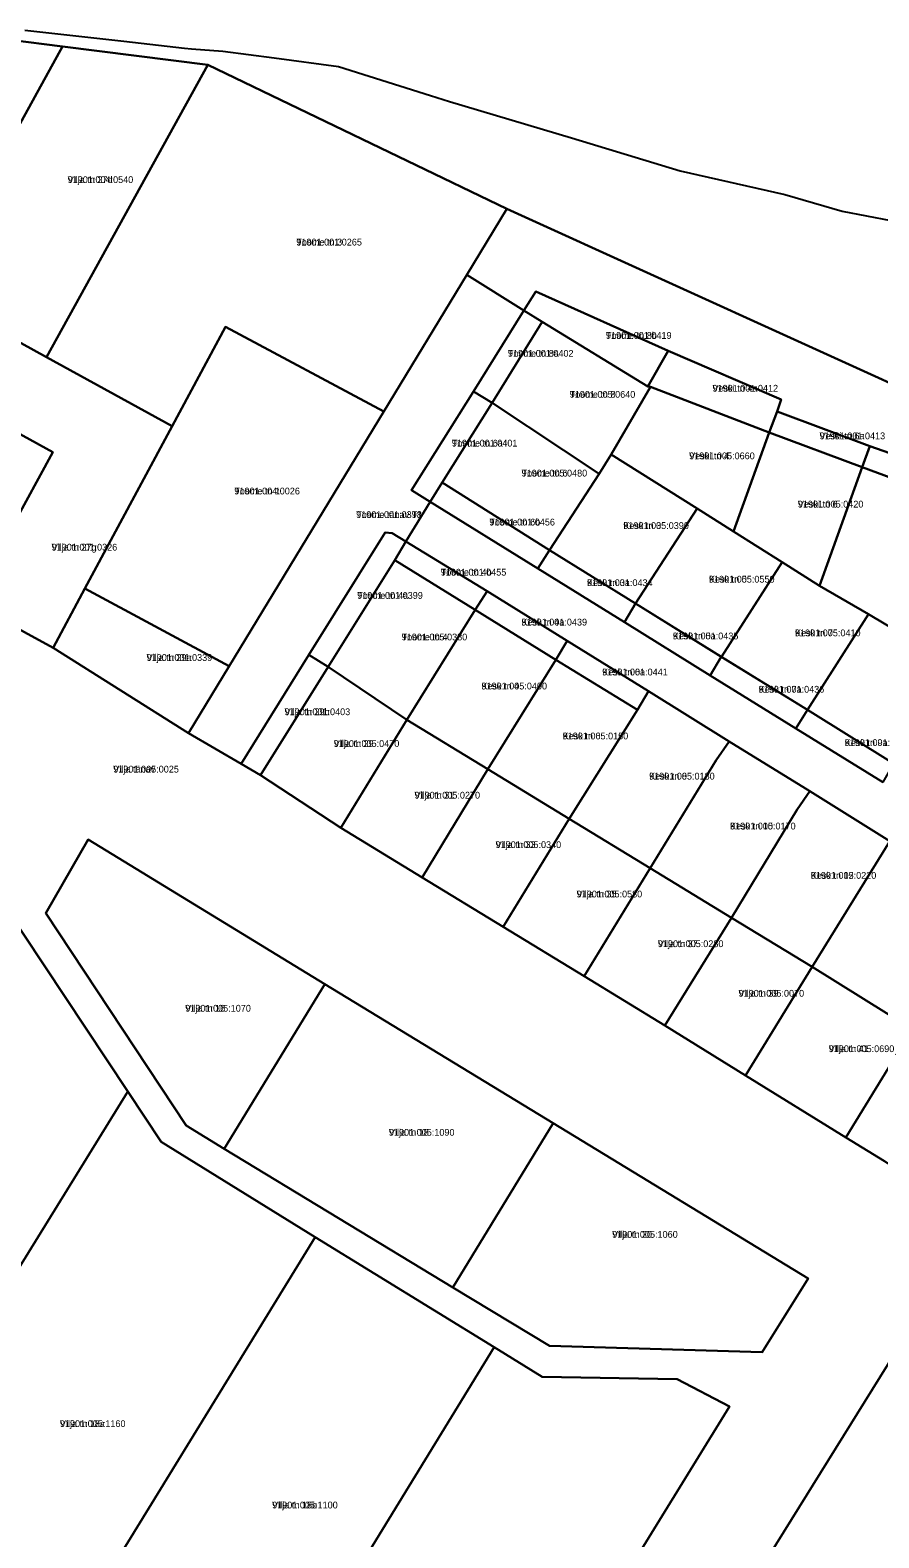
# Model space of a CAD drawing. Extents: x 675810 to 681273, y 6411190 to 6417565.
# Drawn here: x 678832.9 to 679020.6, y 6415637.7 to 6415971.1 of the extents above; entities that cross this region are included whole.
import ezdxf

# ---------------------------------------------------------------- set-up
doc = ezdxf.new("R2010")
doc.units = 0
for name, color, linetype in [('L_AADRESS', 7, 'Continuous'), ('PIIR', 7, 'Continuous'), ('TUNNUS', 7, 'Continuous')]:
    doc.layers.add(name, color=color, linetype=linetype)

msp = doc.modelspace()

# ---------------------------------------------------------------- linework, layer by layer
at = {"layer": 'PIIR'}
for points in [[(678816.91, 6415970.45), (678840.09, 6415967.49), (678810.26, 6415913.35), (678807.69, 6415914.78), (678793.59, 6415922.56), (678787.87, 6415925.69), (678793.94, 6415936.81)], [(678840.09, 6415967.49), (678872.23, 6415963.49), (678836.57, 6415898.82), (678819.7, 6415908.13), (678810.26, 6415913.35)], [(678872.23, 6415963.49), (678938.35, 6415931.63), (678929.48, 6415916.98), (678911.14, 6415886.77), (678876.17, 6415905.51), (678864.38, 6415883.51), (678836.57, 6415898.82)], [(678929.48, 6415916.98), (678938.35, 6415931.63), (679105.26, 6415855.66), (679114.18, 6415850.62), (679165.65, 6415822.55), (679204.44, 6415812.13), (679202.38, 6415803.59), (679183.64, 6415808.38), (679179.78, 6415809.54), (679156.58, 6415819.69), (679127.49, 6415833.35), (679099.54, 6415846.24), (679093.45, 6415836.45), (679084.93, 6415841.89), (679090.32, 6415850.54), (679057.56, 6415864.54), (679037.79, 6415872.39), (679018.58, 6415879.14), (678998.13, 6415886.78), (678998.97, 6415889.41), (678974.02, 6415900.22), (678944.77, 6415913.36), (678942.12, 6415909.13)], [(678879.6, 6415808.84), (678867.97, 6415815.62), (678876.92, 6415830.49), (678911.14, 6415886.77), (678929.48, 6415916.98), (678942.12, 6415909.13), (678931, 6415891.2), (678917.28, 6415869.38), (678921.37, 6415866.84), (678916, 6415858.06), (678913, 6415859.9), (678911.48, 6415860), (678894.53, 6415832.98)], [(678946.19, 6415906.63), (678942.12, 6415909.13), (678944.77, 6415913.36), (678974.02, 6415900.22), (678969.55, 6415892.35)], [(678935.09, 6415888.69), (678931, 6415891.2), (678942.12, 6415909.13), (678946.19, 6415906.63)], [(678811.02, 6415892.58), (678819.7, 6415908.13), (678836.57, 6415898.82), (678864.38, 6415883.51), (678845.04, 6415847.65), (678838.07, 6415834.5), (678819.79, 6415844.47), (678837.94, 6415877.79)], [(678911.14, 6415886.77), (678876.92, 6415830.49), (678845.04, 6415847.65), (678864.38, 6415883.51), (678876.17, 6415905.51)], [(678958.79, 6415873.03), (678935.09, 6415888.69), (678946.19, 6415906.63), (678969.55, 6415892.35), (678970.09, 6415892.21), (678961.44, 6415877.27)], [(678969.55, 6415892.35), (678974.02, 6415900.22), (678998.97, 6415889.41), (678998.13, 6415886.78), (678996.38, 6415882.15), (678970.09, 6415892.21)], [(678819.79, 6415844.47), (678792.22, 6415859.43), (678811.02, 6415892.58), (678837.94, 6415877.79)], [(678988.45, 6415860.25), (678980.42, 6415865.31), (678961.44, 6415877.27), (678970.09, 6415892.21), (678996.38, 6415882.15)], [(678921.37, 6415866.84), (678917.28, 6415869.38), (678931, 6415891.2), (678935.09, 6415888.69), (678924.03, 6415871.11)], [(678924.03, 6415871.11), (678935.09, 6415888.69), (678958.79, 6415873.03), (678947.77, 6415856.12)], [(678996.38, 6415882.15), (678998.13, 6415886.78), (679018.58, 6415879.14), (679016.9, 6415874.51)], [(679016.9, 6415874.51), (679007.49, 6415848.26), (678999.26, 6415853.44), (678988.45, 6415860.25), (678996.38, 6415882.15)], [(679016.9, 6415874.51), (679018.58, 6415879.14), (679037.79, 6415872.39), (679035.82, 6415867.44)], [(678958.79, 6415873.03), (678961.44, 6415877.27), (678980.42, 6415865.31), (678966.81, 6415844.36), (678947.77, 6415856.12)], [(679025.58, 6415837.61), (679018.34, 6415841.95), (679007.49, 6415848.26), (679016.9, 6415874.51), (679035.82, 6415867.44)], [(678921.37, 6415866.84), (678924.03, 6415871.11), (678947.77, 6415856.12), (678945.23, 6415852.06)], [(678980.42, 6415865.31), (678988.45, 6415860.25), (678999.26, 6415853.44), (678985.78, 6415832.52), (678966.81, 6415844.36)], [(678898.82, 6415830.31), (678894.53, 6415832.98), (678911.48, 6415860), (678913, 6415859.9), (678916, 6415858.06), (678913.57, 6415853.92)], [(678913.57, 6415853.92), (678916, 6415858.06), (678933.99, 6415847.04), (678931.37, 6415842.94)], [(678945.23, 6415852.06), (678947.77, 6415856.12), (678966.81, 6415844.36), (678964.34, 6415840.23)], [(678898.82, 6415830.31), (678913.57, 6415853.92), (678931.37, 6415842.94), (678916.25, 6415818.59)], [(678999.26, 6415853.44), (679007.49, 6415848.26), (679018.34, 6415841.95), (679004.82, 6415820.78), (678985.78, 6415832.52)], [(678838.07, 6415834.5), (678845.04, 6415847.65), (678876.92, 6415830.49), (678867.97, 6415815.62)], [(678931.37, 6415842.94), (678933.99, 6415847.04), (678951.71, 6415836.04), (678949.2, 6415831.89)], [(678916.25, 6415818.59), (678931.37, 6415842.94), (678949.2, 6415831.89), (678934.18, 6415807.66)], [(678964.34, 6415840.23), (678966.81, 6415844.36), (678985.77, 6415832.55), (678983.27, 6415828.44)], [(679025.58, 6415837.61), (679037.46, 6415830.49), (679034.34, 6415825.26), (679023.84, 6415808.91), (679004.82, 6415820.78), (679018.34, 6415841.95)], [(678949.2, 6415831.89), (678951.71, 6415836.04), (678969.69, 6415824.91), (678967.2, 6415820.8)], [(678883.9, 6415806.35), (678879.6, 6415808.84), (678894.53, 6415832.98), (678898.82, 6415830.31)], [(678983.27, 6415828.44), (678985.77, 6415832.55), (679004.82, 6415820.78), (679002.22, 6415816.67)], [(678883.9, 6415806.35), (678898.82, 6415830.31), (678916.25, 6415818.59), (678901.67, 6415794.69)], [(678934.18, 6415807.66), (678949.2, 6415831.89), (678967.2, 6415820.8), (678952.11, 6415796.73)], [(678952.11, 6415796.73), (678967.2, 6415820.8), (678969.69, 6415824.91), (678987.5, 6415813.81), (678984.61, 6415809.71), (678970.03, 6415785.8)], [(678901.67, 6415794.69), (678916.25, 6415818.59), (678934.18, 6415807.66), (678919.6, 6415783.76)], [(679002.22, 6415816.67), (679004.82, 6415820.78), (679023.84, 6415808.91), (679021.5, 6415804.84)], [(678970.03, 6415785.8), (678984.61, 6415809.71), (678987.5, 6415813.81), (679005.36, 6415802.84), (679002.54, 6415798.78), (678988.02, 6415774.82)], [(678919.6, 6415783.76), (678934.18, 6415807.66), (678952.11, 6415796.73), (678937.53, 6415772.83)], [(678988.02, 6415774.82), (679002.54, 6415798.78), (679005.36, 6415802.84), (679023.06, 6415791.8), (679005.89, 6415763.94)], [(678937.53, 6415772.83), (678952.11, 6415796.73), (678970.03, 6415785.8), (678955.46, 6415761.9)], [(678836.4, 6415775.85), (678845.75, 6415792.11), (678898.11, 6415760.17), (678875.88, 6415723.72), (678867.41, 6415728.89)], [(678836.4, 6415775.85), (678867.41, 6415728.89), (678875.88, 6415723.72), (678926.43, 6415693.08), (678947.76, 6415680.14), (678994.8, 6415678.72), (679004.98, 6415695.01), (678948.58, 6415729.39), (678898.11, 6415760.17), (678845.75, 6415792.11)], [(679023.06, 6415791.8), (679045.44, 6415777.97), (679027.96, 6415750.19), (679005.89, 6415763.94)], [(678955.46, 6415761.9), (678970.03, 6415785.8), (678988.02, 6415774.82), (678973.27, 6415750.97)], [(678826.86, 6415778.2), (678854.51, 6415736.43), (678814.85, 6415672.09), (678804, 6415678.3), (678777.6, 6415693.42), (678772.39, 6415696.39), (678821.72, 6415781.05)], [(678973.27, 6415750.97), (678988.02, 6415774.82), (679005.89, 6415763.94), (678991.08, 6415739.95)], [(679005.89, 6415763.94), (679027.96, 6415750.19), (679013.28, 6415726.22), (678991.08, 6415739.95)], [(678948.58, 6415729.39), (678926.43, 6415693.08), (678875.88, 6415723.72), (678898.11, 6415760.17)], [(678861.91, 6415725.25), (678895.99, 6415704.22), (678837.49, 6415608.95), (678794.13, 6415637.17), (678783.06, 6415644.39), (678804, 6415678.3), (678814.85, 6415672.09), (678854.51, 6415736.43)], [(679004.98, 6415695.01), (678994.8, 6415678.72), (678947.76, 6415680.14), (678926.43, 6415693.08), (678948.58, 6415729.39)], [(678837.49, 6415608.95), (678895.99, 6415704.22), (678935.54, 6415679.83), (678872.3, 6415576.57), (678847.44, 6415592.33), (678837.37, 6415598.72)], [(679107.25, 6415642.36), (679209.06, 6415573.64), (679235.94, 6415523.12), (679269.34, 6415417.57), (679263.6, 6415410.66), (679213.57, 6415387.53), (679202.07, 6415417.43), (679144.86, 6415396.49), (679135.51, 6415422.06), (679089.93, 6415556), (679070.56, 6415610.67), (679030.28, 6415597.11), (678989.81, 6415623.26), (679030.7, 6415689.1)], [(678946.13, 6415673.31), (678975.99, 6415672.78), (678987.6, 6415666.77), (678919.21, 6415555.67), (678909.73, 6415552.95), (678872.3, 6415576.57), (678935.54, 6415679.83)]]:
    msp.add_lwpolyline(points, close=True, dxfattribs=at)
for points in [[(679418.32, 6415681.66), (679372.45, 6415703.1), (679376.15, 6415709.11), (679339.93, 6415731.36), (679341.68, 6415734.46), (679247.81, 6415787.97), (679240.52, 6415784.31), (679227.34, 6415792.31), (679201.2, 6415798.72), (679202.38, 6415803.59), (679204.44, 6415812.13), (679165.65, 6415822.55), (679175.65, 6415842.58), (679168.11, 6415879.95), (679127.82, 6415898.47), (679110.64, 6415865.76), (679105.26, 6415855.66), (678938.35, 6415931.63), (678872.23, 6415963.49), (678840.09, 6415967.49), (678816.91, 6415970.45)], [(678831.8, 6415971.13), (678853.64, 6415968.7), (678867.04, 6415967.18), (678868.62, 6415967.03), (678875.58, 6415966.49), (678886.92, 6415965), (678901.16, 6415963.12), (678921.5, 6415956.68), (678925.67, 6415955.38), (678952.68, 6415947.28), (678976.7, 6415940.05), (678999.83, 6415934.81), (679012.5, 6415931.11), (679023.26, 6415929.06)], [(679023.06, 6415791.8), (679005.36, 6415802.84), (678987.5, 6415813.81), (678969.69, 6415824.91), (678951.71, 6415836.04), (678933.99, 6415847.04), (678916, 6415858.06), (678921.37, 6415866.84), (678945.23, 6415852.06), (678964.34, 6415840.23), (678983.27, 6415828.44), (679002.22, 6415816.67), (679021.5, 6415804.84)], [(678819.79, 6415844.47), (678838.07, 6415834.5), (678867.97, 6415815.62), (678879.6, 6415808.84), (678883.9, 6415806.35), (678901.67, 6415794.69), (678919.6, 6415783.76), (678937.53, 6415772.83), (678955.46, 6415761.9), (678973.27, 6415750.97), (678991.08, 6415739.95), (679013.28, 6415726.22), (679021.83, 6415720.99), (679025.55, 6415718.7), (679043.31, 6415707.12), (679061.88, 6415695.92), (679080, 6415684.98), (679097.88, 6415673.97), (679115.74, 6415662.92), (679133.58, 6415651.86), (679150.85, 6415640.79), (679155.1, 6415638.2), (679163.58, 6415633.02)], [(678919.21, 6415555.67), (678987.6, 6415666.77), (678975.99, 6415672.78), (678946.13, 6415673.31), (678935.54, 6415679.83), (678895.99, 6415704.22), (678861.91, 6415725.25), (678854.51, 6415736.43), (678826.86, 6415778.2)], [(679021.83, 6415720.99), (679013.28, 6415726.22), (679027.96, 6415750.19)], [(679209.06, 6415573.64), (679107.25, 6415642.36), (679030.7, 6415689.1), (678989.81, 6415623.26)]]:
    msp.add_lwpolyline(points, dxfattribs=at)

# ---------------------------------------------------------------- texts
at = {"layer": 'L_AADRESS'}
for s, p in [('Vilja tn 27d', (678841.24, 6415937.32)), ('Toome tn 3', (678891.8, 6415923.5)), ('Toome tn 8b', (678960.26, 6415902.86)), ('Toome tn 8a', (678938.59, 6415898.9)), ('Veski tn 4a', (678983.82, 6415891.18)), ('Toome tn 8', (678952.25, 6415889.83)), ('Veski tn 6a', (679007.49, 6415880.65)), ('Toome tn 6a', (678926.19, 6415879.04)), ('Veski tn 4', (678978.66, 6415876.23)), ('Toome tn 6', (678941.61, 6415872.41)), ('Toome tn 1', (678878.09, 6415868.45)), ('Veski tn 6', (679002.68, 6415865.55)), ('Toome tänav T1', (678905.04, 6415863.24)), ('Toome tn 6b', (678934.48, 6415861.58)), ('Kesk tn 3', (678964.1, 6415860.82)), ('Vilja tn 27g', (678837.7, 6415856.03)), ('Toome tn 4b', (678923.73, 6415850.5)), ('Kesk tn 3a', (678956.07, 6415848.18)), ('Kesk tn 5', (678983.04, 6415848.95)), ('Toome tn 4a', (678905.27, 6415845.36)), ('Kesk tn 4a', (678941.58, 6415839.46)), ('Kesk tn 7', (679002.06, 6415837.08)), ('Toome tn 4', (678915.09, 6415836.17)), ('Kesk tn 5a', (678975.04, 6415836.4)), ('Vilja tn 29a', (678858.7, 6415831.63)), ('Kesk tn 6a', (678959.43, 6415828.42)), ('Kesk tn 4', (678932.73, 6415825.32)), ('Kesk tn 7a', (678994.03, 6415824.61)), ('Vilja tn 29b', (678889.21, 6415819.63)), ('Kesk tn 6', (678950.69, 6415814.28)), ('Vilja tn 29', (678900.07, 6415812.6)), ('Kesk tn 9a', (679013.05, 6415812.81)), ('Vilja tänav', (678851.33, 6415806.94)), ('Kesk tn 8', (678969.8, 6415805.39)), ('Vilja tn 31', (678917.93, 6415801.18)), ('Kesk tn 10', (678987.7, 6415794.35)), ('Vilja tn 33', (678935.86, 6415790.24)), ('Kesk tn 12', (679005.54, 6415783.44)), ('Vilja tn 35', (678953.78, 6415779.32)), ('Vilja tn 37', (678971.74, 6415768.33)), ('Vilja tn 39', (678989.58, 6415757.37)), ('Vilja tn 16', (678867.25, 6415754.06)), ('Vilja tn 41', (679009.52, 6415745.11)), ('Vilja tn 18', (678912.27, 6415726.62)), ('Vilja tn 20', (678961.63, 6415704.05)), ('Vilja tn 18a', (678839.53, 6415662.19)), ('Vilja tn 18b', (678886.45, 6415644.19))]:
    msp.add_text(s, height=1.5, dxfattribs=at).set_placement(p)
at = {"layer": 'TUNNUS'}
for s, p in [('91901:004:0540', (678841.24, 6415937.32)), ('91901:001:0265', (678891.8, 6415923.5)), ('91901:001:0419', (678960.26, 6415902.86)), ('91901:001:0402', (678938.59, 6415898.9)), ('91901:001:0412', (678983.82, 6415891.18)), ('91901:005:0640', (678952.25, 6415889.83)), ('91901:001:0413', (679007.49, 6415880.65)), ('91901:001:0401', (678926.19, 6415879.04)), ('91901:005:0660', (678978.66, 6415876.23)), ('91901:005:0480', (678941.61, 6415872.41)), ('91901:004:0026', (678878.09, 6415868.45)), ('91901:005:0420', (679002.68, 6415865.55)), ('91901:001:0398', (678905.04, 6415863.24)), ('91901:001:0456', (678934.48, 6415861.58)), ('91901:005:0390', (678964.1, 6415860.82)), ('91901:001:0326', (678837.7, 6415856.03)), ('91901:001:0455', (678923.73, 6415850.5)), ('91901:001:0434', (678956.07, 6415848.18)), ('91901:005:0550', (678983.04, 6415848.95)), ('91901:001:0399', (678905.27, 6415845.36)), ('91901:001:0439', (678941.58, 6415839.46)), ('91901:005:0410', (679002.06, 6415837.08)), ('91901:005:0380', (678915.09, 6415836.17)), ('91901:001:0435', (678975.04, 6415836.4)), ('91901:001:0339', (678858.7, 6415831.63)), ('91901:001:0441', (678959.43, 6415828.42)), ('91901:005:0400', (678932.73, 6415825.32)), ('91901:001:0436', (678994.03, 6415824.61)), ('91901:001:0403', (678889.21, 6415819.63)), ('91901:005:0150', (678950.69, 6415814.28)), ('91901:005:0470', (678900.07, 6415812.6)), ('91901:001:0437', (679013.05, 6415812.81)), ('91901:005:0025', (678851.33, 6415806.94)), ('91901:005:0180', (678969.8, 6415805.39)), ('91901:005:0270', (678917.93, 6415801.18)), ('91901:005:0170', (678987.7, 6415794.35)), ('91901:005:0340', (678935.86, 6415790.24)), ('91901:005:0220', (679005.54, 6415783.44)), ('91901:005:0580', (678953.78, 6415779.32)), ('91901:005:0280', (678971.74, 6415768.33)), ('91901:005:0070', (678989.58, 6415757.37)), ('91901:005:1070', (678867.25, 6415754.06)), ('91901:005:0690', (679009.52, 6415745.11)), ('91901:005:1090', (678912.27, 6415726.62)), ('91901:005:1060', (678961.63, 6415704.05)), ('91901:005:1160', (678839.53, 6415662.19)), ('91901:005:1100', (678886.45, 6415644.19))]:
    msp.add_text(s, height=1.5, dxfattribs=at).set_placement(p)

doc.saveas('drawing.dxf')
